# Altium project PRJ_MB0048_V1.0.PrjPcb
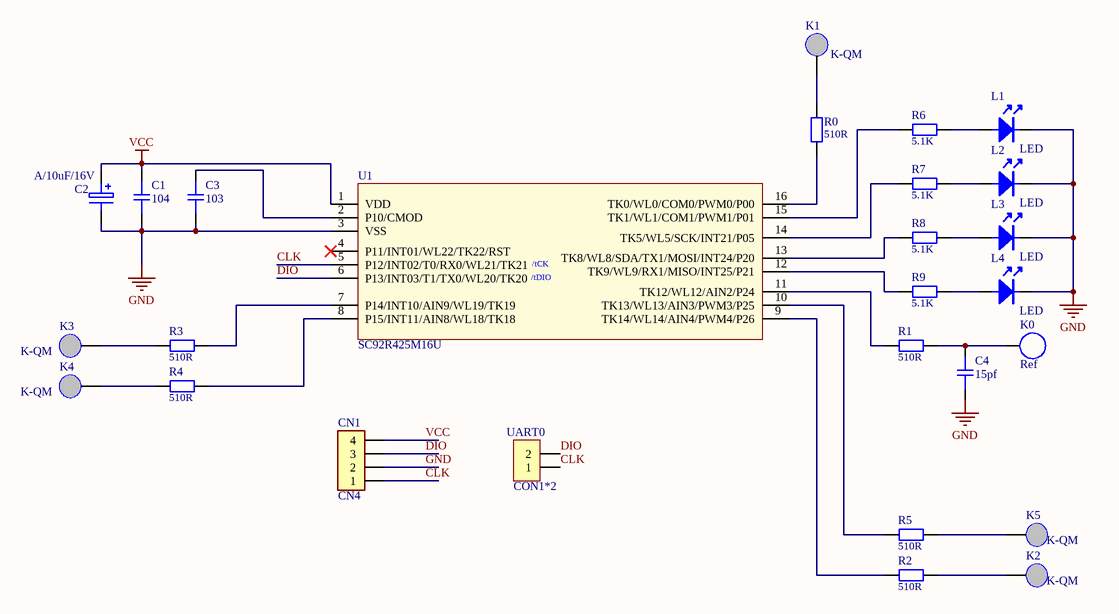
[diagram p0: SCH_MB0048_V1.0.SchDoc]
1 sheet, 27 parts. Net scope: global (net labels, ports and power ports of the same name join across sheets).
Board file: PCB_MB0048_V1.0.PcbDoc

## Sheet SCH_MB0048_V1.0.SchDoc
size A4; SheetNumber: 1; SheetTotal: 1

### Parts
C1  104  [C0603-SMT]
C2  A/10uF/16V  [A-3216]
C3  103  [C0603-SMT]
C4  15pf  [C0603-SMT]
CN1  CN4  [HDR2.54-WS-4P]
K0  Ref
K1  K-QM  [KEY-WL38-2]
K2  K-QM  [KEY-WL38-1]
K3  K-QM  [KEY-WL38-1]
K4  K-QM  [KEY-WL38-1]
K5  K-QM  [KEY-WL38-1]
L1  LED  [LED-0603-SMT]
L2  LED  [LED-0603-SMT]
L3  LED  [LED-0603-SMT]
L4  LED  [LED-0603-SMT]
R0  510R  [R0603-SMT]
R1  510R  [R0603-SMT]
R2  510R  [R0603-SMT]
R3  510R  [R0603-SMT]
R4  510R  [R0603-SMT]
R5  510R  [R0603-SMT]
R6  5.1K  [R0603-SMT]
R7  5.1K  [R0603-SMT]
R8  5.1K  [R0603-SMT]
R9  5.1K  [R0603-SMT]
U1  SC92R425M16U  [SOP16]
UART0  CON1*2  [HDR2.54-WS-2P]

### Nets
GND: C1.1 C2.2 C3.2 C4.2 CN1.2 L1.K L2.K L3.K L4.K U1.3(VSS)
VCC: C1.2 C2.1 CN1.4 U1.1(VDD)
CLK: CN1.1 U1.5(P12/INT02/T0/RX0/WL21/TK21) UART0.1
DIO: CN1.3 U1.6(P13/INT03/T1/TX0/WL20/TK20) UART0.2
NetC3_1: C3.1 U1.2(P10/CMOD)
NetC4_1: C4.1 K0.9 R1.2
NetK1_1: K1.1 R0.1
NetK2_1: K2.1 R2.2
NetK3_1: K3.1 R3.2
NetK4_1: K4.1 R4.2
NetK5_1: K5.1 R5.2
NetL1_A: L1.A R6.2
NetL2_A: L2.A R7.2
NetL3_A: L3.A R8.2
NetL4_A: L4.A R9.2
NetR0_2: R0.2 U1.16(TK0/WL0/COM0/PWM0/P00)
NetR1_1: R1.1 U1.11(TK12/WL12/AIN2/P24)
NetR2_1: R2.1 U1.9(TK14/WL14/AIN4/PWM4/P26)
NetR3_1: R3.1 U1.7(P14/INT10/AIN9/WL19/TK19)
NetR4_1: R4.1 U1.8(P15/INT11/AIN8/WL18/TK18)
NetR5_1: R5.1 U1.10(TK13/WL13/AIN3/PWM3/P25)
NetR6_1: R6.1 U1.15(TK1/WL1/COM1/PWM1/P01)
NetR7_1: R7.1 U1.14(TK5/WL5/SCK/INT21/P05)
NetR8_1: R8.1 U1.13(TK8/WL8/SDA/TX1/MOSI/INT24/P20)
NetR9_1: R9.1 U1.12(TK9/WL9/RX1/MISO/INT25/P21)

Not connected (* = marked no-connect by the designer): U1 4(P11/INT01/WL22/TK22/RST)*

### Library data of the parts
C1 = C_3: C
C2 = T-A/10uF/16V
C3 C4 = C_1: C
CN1 = CN4: 4P-SOCKET
R0-R9 = R: RES
U1 = SC92F8481: 电压:2.4V-5.5V;ROM:128KB;RAM:256B+8KB;32/16/8/4MHz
